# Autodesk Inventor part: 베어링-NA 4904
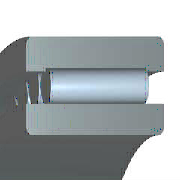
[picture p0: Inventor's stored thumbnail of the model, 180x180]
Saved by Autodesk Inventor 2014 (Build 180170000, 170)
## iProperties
IsCustomPart: 1
Company: 한국ATC센터
Created: 2009-02
Part Number: 베어링-NA 4904
Material: 강철, 연강
Description: 니들 롤러 베어링 - 경계 치수 및 공차
Document SubType Name: Modeling
Standard: KS B 2029
Designer: KYOUNG IL JANG
Standards Organization: KS
Language: ko-KR
Size Designation: NA 4904 - 20 x 37 x 17
Categories: <MemberInstance><Categories><Category DisplayName="샤프트 부품" InternalName="7f7aeb1f-a693-4053-b835-cee3144e0d98" Mnemonic="SHFT"><Category DisplayName="베어링" Inter
Density: 7.86 g/cm^3
Mass: 73.0303 g
Surface Area: 90.2463 cm^2
Volume: 9.29139 cm^3
Vendor: CBT Solutions
Appearance: 강철
Author: KYOUNG IL JANG
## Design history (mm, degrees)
sketch "스케치"
  geometry: L1 (2.429, 16)-(14.571, 16); L2 (14.571, 16)-(14.571, 12.5); L3 (17, 12.5)-(0, 12.5); L4 (2.429, 12.5)-(2.429, 16); L5 (2.429, 14.25)-(14.571, 14.25); L6 (8.5, 14.25)-(8.5, 12.5); L7 (0, 10)-(17, 10); L8 (0, 18.5)-(17, 18.5); L9 (17, 10)-(17, 12.5); L10 (17, 15.65)-(17, 18.5); L11 (2.429, 15.65)-(0, 15.65); L12 (14.571, 15.65)-(17, 15.65); L13 (-6, 0)-(36, 0) reference; L14 (0, -1.9)-(0, 14.9) reference
  constraints: 24 end point, 8 point on line, 3 midpoint, 3 parallel, 3 perpendicular, 2 symmetric about line, 1 horizontal, 1 other
  dimensions: "d6" = 20 diameter of L7 L13 (= WD); "d7" = 25 diameter of L3 L13 (= KID1); "d8" = 37 diameter of L8 L13 (= BD); "d9" = 28.5 diameter of L6.start L13 (= 0.5 x WD + 0.5 x BD); "d10" = 31.3 diameter of L12 L13 (= 0.9 x BD + 0.9 x WD - 0.8 x KID1); "d11" = 32 diameter of L1 L13 (= BD + WD - KID1); "d12" = 2.42857 distance between parallel lines of L14 L4 (= 0.142857 x KB); "d13" = 17 distance between parallel lines of L14 L9 (= KB); "d14" = 14.57143 distance between parallel lines of L14 L2 (= 0.857143 x KB)
revolve "본체" stored, may be unused: angle "d17" = 90 deg
revolve "롤러" stored, may be unused: angle "d18" = 90 deg
pattern_circular "IDS_ARRAYROLLER[SIMPL:T]" dims angle "d2" = 360 deg
body "Solid1"
fillet "모깎기1" dims "d0" = 0.3 (= KRS)
other parameters: "WD" = 20 [user parameter; used in 6 equation terms], "BD" = 37 [user parameter; used in 6 equation terms], "KB" = 17 [user parameter; used in 3 equation terms], "KID1" = 25 [user parameter; used in 4 equation terms], "KRS" = 0.3 [user parameter; used in 1 equation term], "d3" = 0, "d4" = 0, "d5" = 0, "d15" = 0, "d16" = 0, "BC0" = 2.36e+07 [user parameter], "BBA" = 0 [user parameter], "BC" = 1.9e+07 [user parameter], "BR" = 18.5 (= 0.5 x BD) [user parameter]
